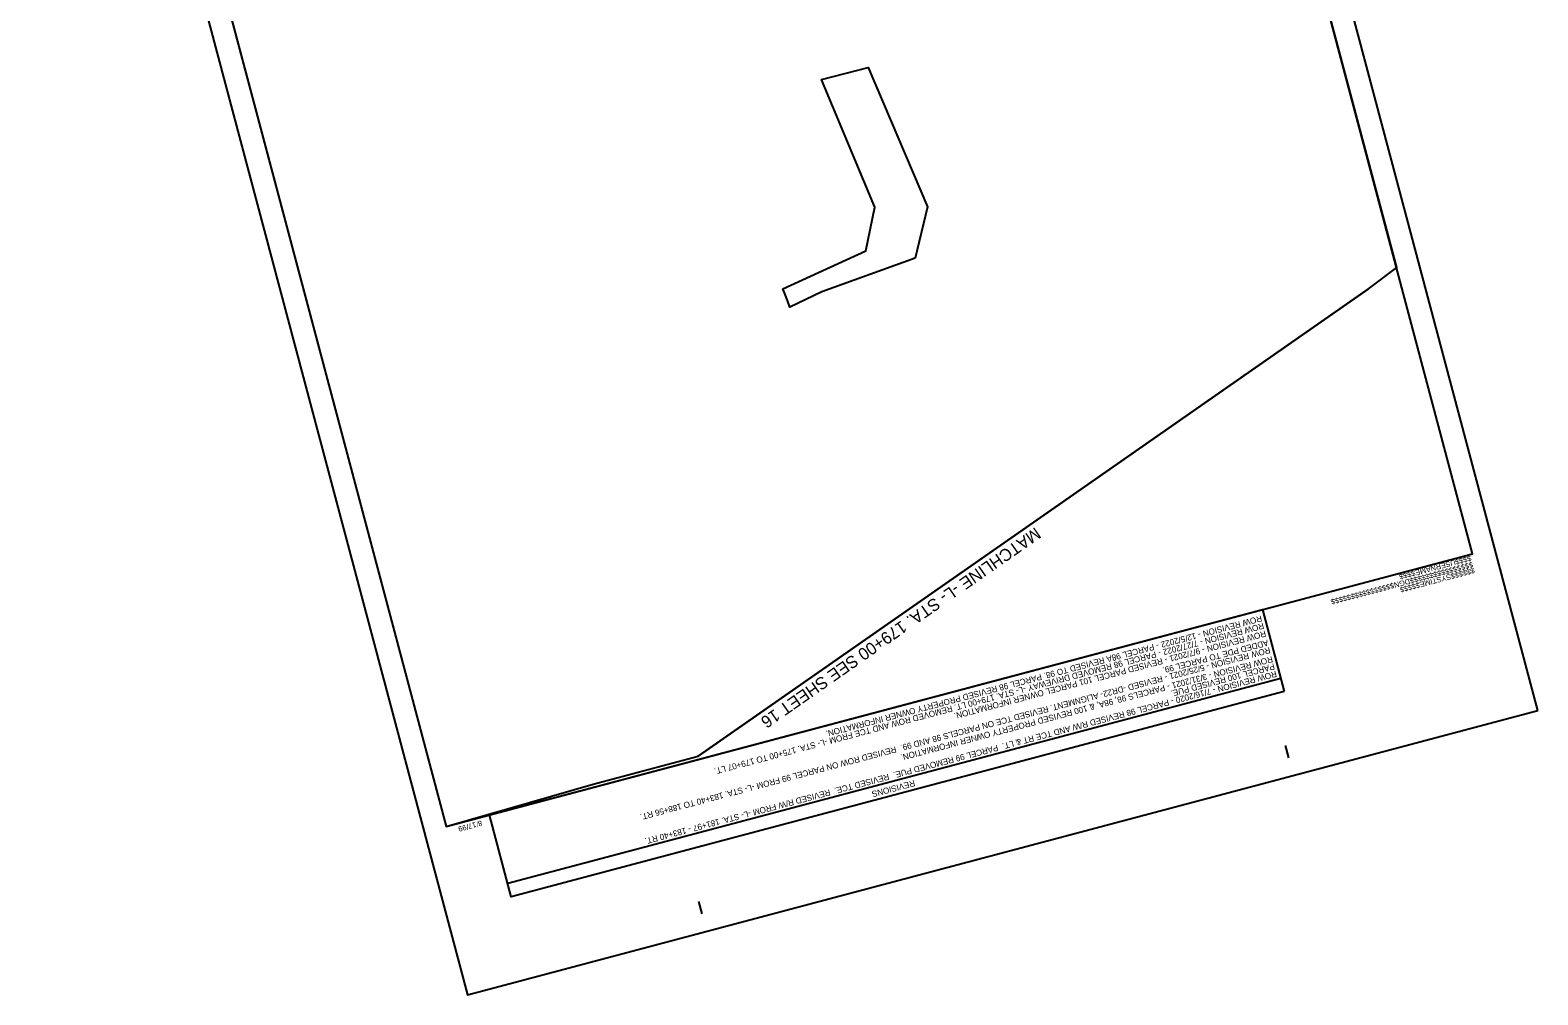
# Model space of a CAD drawing. Extents: x 473963 to 475454, y 503101 to 505009.
# Drawn here: x 473963 to 475454, y 503101 to 504055 of the extents above; entities that cross this region are included whole.
import ezdxf

# ---------------------------------------------------------------- set-up
doc = ezdxf.new("R2010")
doc.units = 0
for name, color, linetype in [('Prop Dimension', 7, 'Continuous'), ('Prop Horizontal Alignment Tick Small', 7, 'Continuous'), ('Prop PHM Label Text', 7, 'Continuous'), ('Prop PHM Label Text White', 7, 'Continuous'), ('Prop PHM White Shape', 7, 'Continuous'), ('Scratch_Level_3', 7, 'Continuous'), ('Scratch_Level_5', 7, 'Continuous')]:
    doc.layers.add(name, color=color, linetype=linetype)

msp = doc.modelspace()

# ---------------------------------------------------------------- linework, layer by layer
at = {"layer": 'Prop Dimension'}
msp.add_line((475199.7, 503413.7), (474435.5, 503210.7), dxfattribs=at)
msp.add_lwpolyline([(475203.1, 503400.7), (474439, 503197.7), (474417.4, 503278.8), (475181.6, 503481.8)], close=True, dxfattribs=at)
at = {"layer": 'Prop Horizontal Alignment Tick Small'}
msp.add_lwpolyline([(474838.3, 503829.3), (474746, 503796), (474714.4, 503781), (474712, 503787.5), (474708.4, 503796.8), (474707.5, 503799.1), (474789.6, 503836.5), (474798.3, 503879.6), (474745.8, 504006), (474791.9, 504017.8), (474850.6, 503880.1)], close=True, dxfattribs=at)
at = {"layer": 'Prop PHM Label Text'}
for p, q in [((475389.4, 503537), (475389.4, 503537)), ((475207.6, 503335.1), (475204.4, 503347.2)), ((474374.6, 503267.4), (474374.6, 503267.4)), ((474627.8, 503181), (474624.5, 503193.1))]:
    msp.add_line(p, q, dxfattribs=at)
msp.add_lwpolyline([(473989.4, 504717.2), (474374.6, 503267.4), (475389.4, 503537), (475004.2, 504986.7)], close=True, dxfattribs=at)
at = {"layer": 'Prop PHM Label Text White'}
msp.add_line((475286.3, 503799), (474623.6, 503336.7), dxfattribs=at)
at = {"layer": 'Scratch_Level_3'}
msp.add_lwpolyline([(474208.5, 504568.4), (474040.8, 504523.8), (474374.6, 503267.4), (474520, 503309.1), (474623.6, 503336.7), (475286.3, 503799), (475314.3, 503820), (475048, 504821.9), (474956.2, 504797.2), (474937.1, 504862.2), (474845, 504732.8), (474845, 504732.8), (474213.6, 504656.4)], close=True, dxfattribs=at)
at = {"layer": 'Scratch_Level_5'}
msp.add_lwpolyline([(475453.9, 503381.9), (475021.6, 505008.9), (473963.3, 504727.8), (474395.6, 503100.7)], close=True, dxfattribs=at)

# ---------------------------------------------------------------- texts
at = {"layer": 'Prop Dimension'}
for s, p in [('ROW REVISION - 7/27/2022 - PARCEL 98 REMOVED DRIVEWAY -L- STA. 179+00 LT. REMOVED ROW AND TCE FROM -L- STA. 175+00 TO 179+07 LT. ', (475182.2, 503468.8)), ('ROW REVISION - 12/5/2022 - PARCEL 98A REVISED TO 98. PARCEL 98 REVISED PROPERTY OWNER INFORMATION. ', (475180.2, 503476.1)), ('ROW REVISION - 9/7/2021 - REVISED PARCEL 101 PARCEL OWNER INFORMATION.', (475184.2, 503461.1)), ('ADDED PDE TO PARCEL 99. ', (475186.6, 503452.1)), ('ROW REVISION - 5/25/2021 - REVISED -DR22- ALIGNMENT. REVISED TCE ON PARCELS 98 AND 99.  REVISED ROW ON PARCEL 99 FROM -L- STA. 183+40 TO 188+56 RT. ', (475188.5, 503444.8)), ('ROW REVISION - 3/31/2021 - PARCELS 98, 98A, & 100 REVISED PROPERTY OWNER INFORMATION. ', (475190.9, 503435.8)), ('ROW REVISION - 7/16/2020 - PARCEL 98 REVISED R/W AND TCE RT & LT.  PARCEL 99 REMOVED PUE.  REVISED TCE.  REVISED R/W FROM -L- STA. 181+97 - 183+40 RT.', (475194.8, 503421.3)), ('PARCEL 100 REVISED PUE.', (475192.8, 503428.6)), ('REVISIONS', (474837.2, 503313.2))]:
    msp.add_text(s, height=6, rotation=194.8779, dxfattribs=at).set_placement(p)
at = {"layer": 'Prop PHM Label Text'}
for s, p in [('$$$$$$$$$$$$$$$$DGN$$$$$$$$$$$$$$$$', (475389, 503529)), ('$$$$USERNAME$$$$', (475387.3, 503535.3)), ('$$$$$$SYSTIME$$$$$', (475390.6, 503523.2)), ('8/17/99', (474409.4, 503273.3))]:
    msp.add_text(s, height=5.25, rotation=194.8779, dxfattribs=at).set_placement(p)
at = {"layer": 'Prop PHM White Shape'}
msp.add_text('MATCHLINE -L- STA. 179+00 SEE SHEET 16', height=12, rotation=214.9001, dxfattribs=at).set_placement((474957, 503563.7))

doc.saveas('drawing.dxf')
